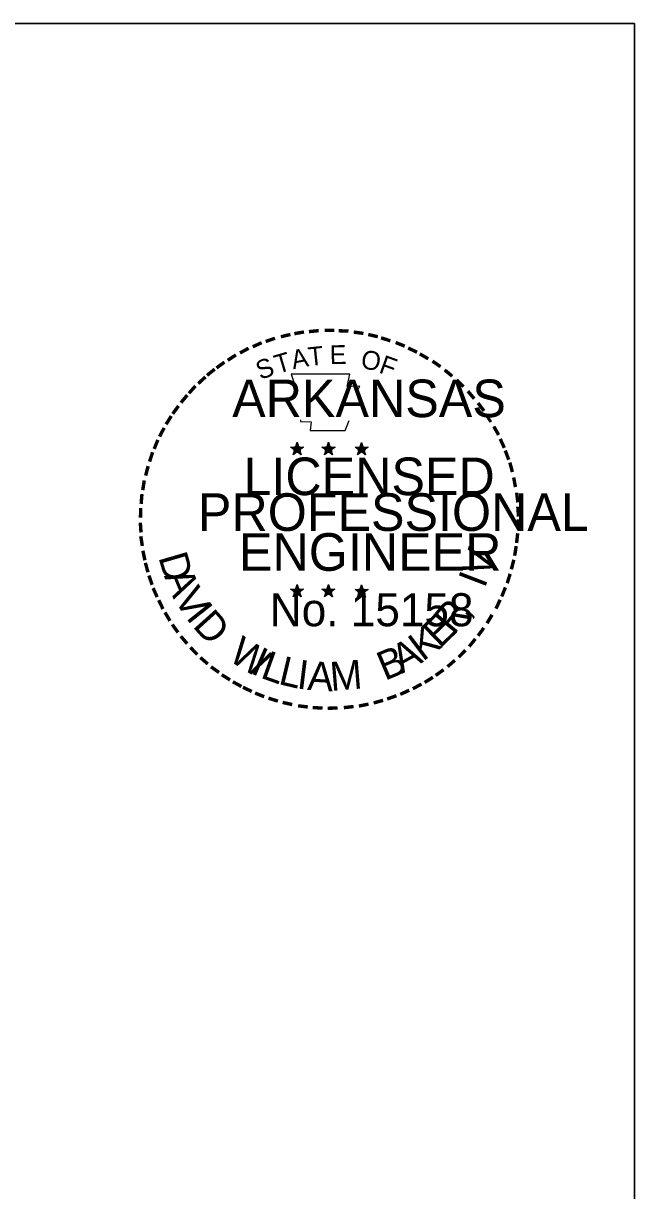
# Model space of a CAD drawing. Extents: x 31847 to 33828, y 52928 to 59118.
# Drawn here: x 33402.6 to 33570.4, y 56245.7 to 56566.1 of the extents above; entities that cross this region are included whole.
import ezdxf

# ---------------------------------------------------------------- set-up
doc = ezdxf.new("R2010")
doc.units = 0
for name, color, linetype in [('Default', 7, 'Continuous'), ('DSN_DRFT_Junk-No-Plot', 7, 'Continuous'), ('R_Border PE', 7, 'Continuous')]:
    doc.layers.add(name, color=color, linetype=linetype)

msp = doc.modelspace()

# ---------------------------------------------------------------- linework, layer by layer
at = {"layer": 'Default'}
msp.add_lwpolyline([(31870.42, 56566.09), (31870.42, 55466.09), (33570.42, 55466.09), (33570.42, 56566.09)], close=True, dxfattribs=at)
msp.add_lwpolyline([(31870.42, 56566.09), (31870.42, 55466.09), (33570.42, 55466.09), (33570.42, 56566.09)], close=True, dxfattribs=at)
at = {"layer": 'DSN_DRFT_Junk-No-Plot'}
msp.add_lwpolyline([(31870.42, 56566.09), (33570.42, 56566.09), (33570.42, 55466.09), (31870.42, 55466.09)], close=True, dxfattribs=at)
at = {"layer": 'R_Border PE'}
for p, q in [((33477.78, 56451.11), (33477.57, 56449.81)), ((33477.78, 56449.22), (33477.78, 56451.11)), ((33477.78, 56451.11), (33478.03, 56449.82)), ((33486.39, 56451.11), (33486.18, 56449.81)), ((33486.39, 56449.22), (33486.39, 56451.11)), ((33486.39, 56451.11), (33486.64, 56449.82)), ((33495.49, 56451.04), (33495.28, 56449.75)), ((33495.49, 56449.16), (33495.49, 56451.04)), ((33495.49, 56451.04), (33495.74, 56449.76)), ((33475.98, 56449.8), (33477.78, 56449.22)), ((33475.98, 56449.8), (33477.29, 56449.56)), ((33475.98, 56449.8), (33477.2, 56449.17)), ((33476.67, 56447.69), (33477.78, 56449.22)), ((33476.67, 56447.69), (33477.32, 56448.95)), ((33476.67, 56447.69), (33477.77, 56448.81)), ((33478.88, 56447.69), (33477.77, 56448.8)), ((33479.57, 56449.8), (33477.78, 56449.22)), ((33478.88, 56447.69), (33477.78, 56449.22)), ((33479.57, 56449.8), (33478.09, 56449.54)), ((33478.88, 56447.69), (33478.17, 56449.19)), ((33479.57, 56449.8), (33478.52, 56449.27)), ((33484.59, 56449.8), (33486.39, 56449.22)), ((33484.59, 56449.8), (33485.9, 56449.56)), ((33484.59, 56449.8), (33485.81, 56449.17)), ((33485.28, 56447.69), (33486.39, 56449.22)), ((33485.28, 56447.69), (33485.93, 56448.95)), ((33485.28, 56447.69), (33486.38, 56448.81)), ((33487.49, 56447.69), (33486.38, 56448.8)), ((33488.18, 56449.8), (33486.39, 56449.22)), ((33487.49, 56447.69), (33486.39, 56449.22)), ((33488.18, 56449.8), (33486.71, 56449.54)), ((33487.49, 56447.69), (33486.78, 56449.19)), ((33488.18, 56449.8), (33487.13, 56449.27)), ((33493.69, 56449.73), (33495.49, 56449.16)), ((33493.69, 56449.73), (33494.99, 56449.5)), ((33493.69, 56449.73), (33494.91, 56449.11)), ((33494.37, 56447.63), (33495.49, 56449.16)), ((33494.37, 56447.63), (33495.02, 56448.89)), ((33494.37, 56447.63), (33495.48, 56448.75)), ((33496.58, 56447.63), (33495.48, 56448.73)), ((33497.28, 56449.73), (33495.49, 56449.16)), ((33496.58, 56447.63), (33495.49, 56449.16)), ((33497.28, 56449.73), (33495.8, 56449.48)), ((33496.58, 56447.63), (33495.88, 56449.13)), ((33497.28, 56449.73), (33496.22, 56449.21)), ((33475.96, 56410.75), (33477.76, 56410.18)), ((33475.96, 56410.75), (33477.26, 56410.52)), ((33475.96, 56410.75), (33477.18, 56410.12)), ((33476.65, 56408.64), (33477.76, 56410.18)), ((33476.65, 56408.64), (33477.3, 56409.9)), ((33476.65, 56408.64), (33477.75, 56409.76)), ((33477.76, 56412.06), (33477.55, 56410.76)), ((33478.86, 56408.64), (33477.75, 56409.75)), ((33477.76, 56410.18), (33477.76, 56412.06)), ((33477.76, 56412.06), (33478.01, 56410.77)), ((33479.55, 56410.75), (33477.76, 56410.18)), ((33478.86, 56408.64), (33477.76, 56410.18)), ((33479.55, 56410.75), (33478.07, 56410.5)), ((33478.86, 56408.64), (33478.15, 56410.15)), ((33479.55, 56410.75), (33478.5, 56410.22)), ((33484.57, 56410.75), (33486.37, 56410.18)), ((33484.57, 56410.75), (33485.87, 56410.52)), ((33484.57, 56410.75), (33485.79, 56410.12)), ((33485.25, 56408.64), (33486.37, 56410.18)), ((33485.25, 56408.64), (33485.9, 56409.9)), ((33485.25, 56408.64), (33486.35, 56409.76)), ((33486.37, 56412.06), (33486.15, 56410.76)), ((33487.46, 56408.64), (33486.35, 56409.75)), ((33486.37, 56410.18), (33486.37, 56412.06)), ((33486.37, 56412.06), (33486.62, 56410.77)), ((33488.15, 56410.75), (33486.37, 56410.18)), ((33487.46, 56408.64), (33486.37, 56410.18)), ((33488.15, 56410.75), (33486.68, 56410.5)), ((33487.46, 56408.64), (33486.76, 56410.15)), ((33488.15, 56410.75), (33487.1, 56410.22)), ((33493.68, 56410.7), (33495.48, 56410.12)), ((33493.68, 56410.7), (33494.98, 56410.46)), ((33493.68, 56410.7), (33494.9, 56410.07)), ((33494.36, 56408.59), (33495.48, 56410.12)), ((33494.36, 56408.59), (33495.01, 56409.85)), ((33494.36, 56408.59), (33495.47, 56409.71)), ((33495.48, 56412.01), (33495.26, 56410.71)), ((33496.57, 56408.59), (33495.47, 56409.7)), ((33495.48, 56410.12), (33495.48, 56412.01)), ((33495.48, 56412.01), (33495.73, 56410.72)), ((33497.27, 56410.7), (33495.48, 56410.12)), ((33496.57, 56408.59), (33495.48, 56410.12)), ((33497.27, 56410.7), (33495.79, 56410.44)), ((33496.57, 56408.59), (33495.87, 56410.09)), ((33497.27, 56410.7), (33496.21, 56410.17))]:
    msp.add_line(p, q, dxfattribs=at)
for points in [[(33476.19, 56469.79), (33477.58, 56465.53)], [(33494.3, 56465.04), (33495.03, 56466.5), (33491.5, 56466.38), (33492.26, 56469.79), (33476.19, 56469.79)], [(33478.73, 56457.3), (33478.73, 56456.85), (33481.63, 56456.75), (33481.35, 56454.31), (33491, 56454.31), (33492.03, 56457.08)], [(33477.78, 56451.11), (33478.88, 56447.69), (33475.98, 56449.8), (33479.57, 56449.8), (33476.67, 56447.69), (33477.78, 56451.11)], [(33486.39, 56451.11), (33487.49, 56447.69), (33484.59, 56449.8), (33488.18, 56449.8), (33485.28, 56447.69), (33486.39, 56451.11)], [(33495.49, 56451.04), (33496.58, 56447.63), (33493.69, 56449.73), (33497.28, 56449.73), (33494.37, 56447.63), (33495.49, 56451.04)], [(33477.76, 56412.06), (33478.86, 56408.64), (33475.96, 56410.75), (33479.55, 56410.75), (33476.65, 56408.64), (33477.76, 56412.06)], [(33486.37, 56412.06), (33487.46, 56408.64), (33484.57, 56410.75), (33488.15, 56410.75), (33485.25, 56408.64), (33486.37, 56412.06)], [(33495.48, 56412.01), (33496.57, 56408.59), (33493.68, 56410.7), (33497.27, 56410.7), (33494.36, 56408.59), (33495.48, 56412.01)]]:
    msp.add_lwpolyline(points, dxfattribs=at)
for centre, radius in [((33477.77, 56449.22), 0.888), ((33477.77, 56449.22), 0.745), ((33477.77, 56449.22), 0.597), ((33477.77, 56449.22), 0.511), ((33477.77, 56449.22), 0.385), ((33477.77, 56449.22), 0.255), ((33477.77, 56449.22), 0.153), ((33486.39, 56449.22), 0.888), ((33486.39, 56449.22), 0.745), ((33486.39, 56449.22), 0.597), ((33486.39, 56449.22), 0.511), ((33486.39, 56449.22), 0.385), ((33486.39, 56449.22), 0.255), ((33486.39, 56449.22), 0.153), ((33495.48, 56449.16), 0.888), ((33495.48, 56449.16), 0.745), ((33495.48, 56449.16), 0.597), ((33495.48, 56449.16), 0.511), ((33495.48, 56449.16), 0.385), ((33495.48, 56449.16), 0.255), ((33495.48, 56449.16), 0.153), ((33477.75, 56410.17), 0.888), ((33477.75, 56410.17), 0.745), ((33477.75, 56410.17), 0.597), ((33477.75, 56410.17), 0.511), ((33477.75, 56410.17), 0.385), ((33477.75, 56410.17), 0.255), ((33477.75, 56410.17), 0.153), ((33486.36, 56410.17), 0.888), ((33486.36, 56410.17), 0.745), ((33486.36, 56410.17), 0.597), ((33486.36, 56410.17), 0.511), ((33486.36, 56410.17), 0.385), ((33486.36, 56410.17), 0.255), ((33486.36, 56410.17), 0.153), ((33495.47, 56410.12), 0.888), ((33495.47, 56410.12), 0.745), ((33495.47, 56410.12), 0.597), ((33495.47, 56410.12), 0.511), ((33495.47, 56410.12), 0.385), ((33495.47, 56410.12), 0.255), ((33495.47, 56410.12), 0.153)]:
    msp.add_circle(centre, radius, dxfattribs=at)

# ---------------------------------------------------------------- texts
for s, height, rotation, p in [('-', 8.25, 19.1761, (33469.74, 56475.6)), ('-', 8.25, 13.6302, (33473.6, 56476.85)), ('-', 8.25, 10.2193, (33477.1, 56477.68)), ('-', 8.25, 5.8968, (33480.86, 56478.25)), ('-', 8.25, 0.1862, (33484.84, 56478.62)), ('-', 8.25, 357.743, (33488.57, 56478.55)), ('-', 8.25, 352.1617, (33492.4, 56478.26)), ('-', 8.25, 347.2049, (33496.11, 56477.68)), ('-', 8.25, 342.3362, (33499.38, 56476.88)), ('-', 8.25, 28.7918, (33463.2, 56472.58)), ('-', 8.25, 24.3072, (33466.47, 56474.22)), ('A', 5.16, 11.2132, (33476.68, 56471.13)), ('T', 5.16, 6.0228, (33481.06, 56471.99)), ('E', 5.16, 0.8323, (33486.76, 56472.56)), ('O', 5.16, 350.4515, (33495.03, 56471.47)), ('-', 8.25, 337.8551, (33503.17, 56475.73)), ('-', 8.25, 334.1211, (33506.43, 56474.33)), ('-', 8.25, 36.2317, (33457.14, 56468.64)), ('-', 8.25, 34.0636, (33460.12, 56470.67)), ('S', 5.16, 21.594, (33467.71, 56468.13)), ('T', 5.16, 16.4036, (33472.42, 56469.84)), ('F', 5.16, 340.0707, (33499.95, 56470.3)), ('-', 8.25, 329.6409, (33509.41, 56472.87)), ('-', 8.25, 325.8627, (33512.73, 56471.01)), ('-', 8.25, 38.9507, (33454.69, 56466.69)), ('-', 8.25, 320.5297, (33515.87, 56468.81)), ('-', 8.25, 48.4231, (33450.15, 56462.07)), ('-', 8.25, 42.9622, (33452.46, 56464.54)), ('-', 8.25, 315.5786, (33518.96, 56466.3)), ('-', 8.25, 50.6142, (33448.07, 56459.57)), ('-', 8.25, 309.8797, (33521.9, 56463.46)), ('-', 8.25, 54.2325, (33445.94, 56456.64)), ('-', 8.25, 306.6522, (33524.6, 56460.36)), ('-', 8.25, 58.0706, (33444.26, 56453.93)), ('-', 7.22, 303.6753, (33527.11, 56457.43)), ('-', 8.25, 62.8713, (33442.65, 56450.76)), ('-', 8.25, 299.6684, (33528.75, 56454.3)), ('-', 8.25, 67.7743, (33441.31, 56447.61)), ('-', 8.25, 294.6628, (33530.42, 56451.14)), ('-', 8.25, 72.3945, (33440.18, 56444.36)), ('-', 8.25, 290.5728, (33531.75, 56448.17)), ('-', 8.25, 75.461, (33439.17, 56440.68)), ('-', 8.25, 285.1233, (33532.96, 56445.18)), ('-', 8.25, 280.5493, (33533.99, 56441.35)), ('-', 8.25, 81.2013, (33438.49, 56437)), ('-', 8.25, 85.1863, (33438.1, 56433.44)), ('-', 8.25, 276.5962, (33534.82, 56437.39)), ('-', 8.25, 89.0622, (33437.97, 56429.83)), ('-', 8.25, 274.3301, (33535.13, 56433.67)), ('-', 8.25, 94.1959, (33438.15, 56426.09)), ('-', 8.25, 269.9407, (33535.31, 56430.41)), ('-', 8.25, 98.9479, (33438.52, 56422.65)), ('-', 8.25, 263.5172, (33535.21, 56426.98)), ('V', 7.94, 72.6573, (33530.38, 56413.6)), ('-', 8.25, 260.9953, (33534.84, 56423.6)), ('-', 8.25, 101.7149, (33439.22, 56418.87)), ('D', 7.94, 286.2848, (33439.67, 56419.58)), ('-', 8.25, 255.7626, (33534.28, 56420.11)), ('-', 8.25, 105.4578, (33440.05, 56415.8)), ('I', 7.94, 69.0301, (33529.24, 56410.82)), ('-', 8.25, 109.0874, (33441.16, 56412.55)), ('A', 7.94, 292.7835, (33441.18, 56414.42)), ('V', 7.94, 300.7936, (33443.83, 56408.33)), ('-', 8.25, 252.8681, (33533.34, 56416.39)), ('-', 8.25, 114.0643, (33442.47, 56409.47)), ('-', 8.25, 247.8887, (33532.19, 56412.92)), ('-', 8.25, 115.7289, (33444.04, 56406.29)), ('I', 7.94, 308.3502, (33447.09, 56402.99)), ('R', 7.94, 50.3651, (33520.73, 56397.98)), ('-', 8.25, 244.6197, (33530.84, 56409.68)), ('-', 8.25, 120.4471, (33445.88, 56403.27)), ('D', 7.94, 311.9774, (33448.89, 56400.59)), ('E', 7.94, 44.0175, (33516.94, 56394.34)), (',', 7.94, 57.4684, (33524.46, 56402.53)), ('-', 8.25, 239.0712, (33528.81, 56405.8)), ('-', 8.25, 125.8934, (33447.96, 56400.37)), ('K', 7.94, 36.9143, (33512.26, 56390.78)), ('-', 8.25, 233.8452, (33526.74, 56402.44)), ('-', 8.25, 130.7181, (33450.34, 56397.53)), ('W', 7.94, 328.0731, (33458.58, 56391.48)), ('A', 7.94, 28.9042, (33506.49, 56387.49)), ('-', 8.25, 231.2538, (33524.52, 56399.52)), ('-', 8.25, 134.2238, (33453.01, 56394.72)), ('I', 7.94, 336.6877, (33464.7, 56387.82)), ('L', 7.94, 340.3149, (33467.43, 56386.56)), ('B', 7.94, 22.8589, (33501.87, 56385.57)), ('-', 8.25, 225.7653, (33522.05, 56396.61)), ('-', 8.25, 138.9338, (33455.72, 56392.33)), ('-', 8.25, 144.6463, (33458.58, 56390.23)), ('L', 7.94, 346.6625, (33472.38, 56384.79)), ('I', 7.94, 353.0101, (33477.49, 56383.57)), ('A', 7.94, 356.6373, (33480.47, 56383.13)), ('M', 7.94, 4.6473, (33487.09, 56382.83)), ('-', 8.25, 221.0851, (33519.36, 56393.99)), ('-', 8.25, 148.0898, (33461.47, 56388.32)), ('-', 8.25, 212.2491, (33513.77, 56389.56)), ('-', 8.25, 215.7363, (33516.53, 56391.55)), ('-', 8.25, 151.5704, (33464.46, 56386.64)), ('-', 8.25, 154.6002, (33467.15, 56385.37)), ('-', 8.25, 204.2516, (33507.68, 56386.13)), ('-', 8.25, 207.3568, (33510.9, 56387.77)), ('-', 8.25, 158.5612, (33470.37, 56384.06)), ('-', 8.25, 162.7983, (33473.91, 56382.96)), ('-', 8.25, 167.5555, (33477.6, 56382.12)), ('-', 8.25, 195.4743, (33501, 56383.47)), ('-', 8.25, 199.4643, (33504.43, 56384.7)), ('-', 8.25, 173.1155, (33481.58, 56381.55)), ('-', 8.25, 176.5183, (33485.44, 56381.28)), ('-', 8.25, 181.5918, (33489.27, 56381.37)), ('-', 8.25, 185.8167, (33493.44, 56381.77)), ('-', 8.25, 191.2858, (33497.24, 56382.45))]:
    msp.add_text(s, height=height, rotation=rotation, dxfattribs=at).set_placement(p)
for s, height, p in [('ARKANSAS', 10.312, (33459.96, 56458)), ('LICENSED', 10.312, (33463.05, 56436.6)), ('PROFESSIONAL', 10.3125, (33450.55, 56426.78)), ('ENGINEER', 10.312, (33461.83, 56415.83)), ('No. 15158', 9.06, (33470.29, 56400.61)), ('AAMU', 0.000103, (33486.02, 56382.8))]:
    msp.add_text(s, height=height, dxfattribs=at).set_placement(p)

doc.saveas('drawing.dxf')
